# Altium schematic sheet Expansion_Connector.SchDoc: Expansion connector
size A4; Project: STM32MP15-DISCO PI; Date: Not used; ApprovedBy: Not used; CheckedBy: Not used; Author: Not used; CompanyName: STMicroelectronics; DrawnBy: Not used; Engineer: Not used; Organization: Not used; Address1: Not used; Address2: Not used; Address3: Not used; Address4: Not used; DocumentNumber: 14; Revision: Not used; SheetNumber: 14; SheetTotal: 17
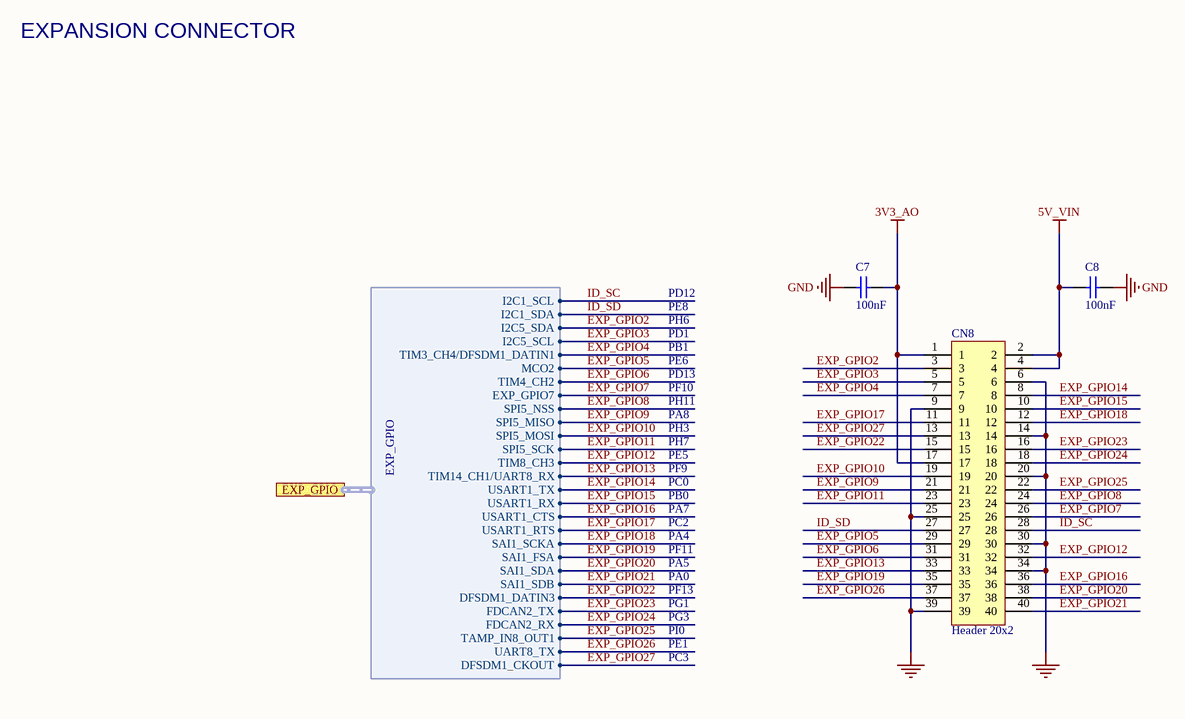
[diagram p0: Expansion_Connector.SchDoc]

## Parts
C7  value 100nF  [C0402]  (hidden comment: Capacitor)
C8  value 100nF  [C0402]  (hidden comment: Capacitor)
CN8  Header 20x2  [CON_SAMTEC_TSW-120-07-G-D]

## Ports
EXP_GPIO (harness EXP_GPIO)

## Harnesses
EXP_GPIO: I2C1_SCL, I2C1_SDA, I2C5_SDA, MCO2, TIM8_CH3, DFSDM1_DATIN3, SPI5_NSS, SPI5_MISO, SPI5_MOSI, SPI5_SCK, TIM4_CH2, USART1_TX, USART1_RX, USART1_CTS, USART1_RTS, UART8_TX, TIM14_CH1/UART8_RX, FDCAN2_TX, FDCAN2_RX, DFSDM1_CKOUT, TIM3_CH4/DFSDM1_DATIN1, I2C5_SCL, SAI1_SCKA, SAI1_FSA, SAI1_SDA, SAI1_SDB, TAMP_IN8_OUT1, EXP_GPIO7

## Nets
3V3_AO: C7.1 CN8.1 CN8.17
5V_VIN: C8.2 CN8.2 CN8.4
GND: C7.2 C8.1 CN8.6 CN8.9 CN8.14 CN8.20 CN8.25 CN8.30 CN8.34 CN8.39
EXP_GPIO2: CN8.3 ; port EXP_GPIO.I2C5_SDA
EXP_GPIO3: CN8.5 ; port EXP_GPIO.I2C5_SCL
EXP_GPIO4: CN8.7 ; port EXP_GPIO.TIM3_CH4/DFSDM1_DATIN1
EXP_GPIO5: CN8.29 ; port EXP_GPIO.MCO2
EXP_GPIO6: CN8.31 ; port EXP_GPIO.TIM4_CH2
EXP_GPIO7: CN8.26 ; port EXP_GPIO.EXP_GPIO7
EXP_GPIO8: CN8.24 ; port EXP_GPIO.SPI5_NSS
EXP_GPIO9: CN8.21 ; port EXP_GPIO.SPI5_MISO
EXP_GPIO10: CN8.19 ; port EXP_GPIO.SPI5_MOSI
EXP_GPIO11: CN8.23 ; port EXP_GPIO.SPI5_SCK
EXP_GPIO12: CN8.32 ; port EXP_GPIO.TIM8_CH3
EXP_GPIO13: CN8.33 ; port EXP_GPIO.TIM14_CH1/UART8_RX
EXP_GPIO14: CN8.8 ; port EXP_GPIO.USART1_TX
EXP_GPIO15: CN8.10 ; port EXP_GPIO.USART1_RX
EXP_GPIO16: CN8.36 ; port EXP_GPIO.USART1_CTS
EXP_GPIO17: CN8.11 ; port EXP_GPIO.USART1_RTS
EXP_GPIO18: CN8.12 ; port EXP_GPIO.SAI1_SCKA
EXP_GPIO19: CN8.35 ; port EXP_GPIO.SAI1_FSA
EXP_GPIO20: CN8.38 ; port EXP_GPIO.SAI1_SDA
EXP_GPIO21: CN8.40 ; port EXP_GPIO.SAI1_SDB
EXP_GPIO22: CN8.15 ; port EXP_GPIO.DFSDM1_DATIN3
EXP_GPIO23: CN8.16 ; port EXP_GPIO.FDCAN2_TX
EXP_GPIO24: CN8.18 ; port EXP_GPIO.FDCAN2_RX
EXP_GPIO25: CN8.22 ; port EXP_GPIO.TAMP_IN8_OUT1
EXP_GPIO26: CN8.37 ; port EXP_GPIO.UART8_TX
EXP_GPIO27: CN8.13 ; port EXP_GPIO.DFSDM1_CKOUT
ID_SC: CN8.28 ; port EXP_GPIO.I2C1_SCL
ID_SD: CN8.27 ; port EXP_GPIO.I2C1_SDA

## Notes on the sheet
- EXPANSION CONNECTOR
- PD12
- PE8
- PB1
- PD1
- PH6
- PE6
- PD13
- PF10
- PA8
- PH3
- PH7
- PH11
- PE5
- PF9
- PA7
- PC0
- PB0
- PF11
- PA4
- PA5
- PA0
- PC2
- PF13
- PG3
- PG1
- PI0
- PE1
- PC3

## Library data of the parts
C7 C8 = MCD-00006: Capacitor, MLCC, 100nF, 16V, X7R, +/-10%, 0402, T=0.5mm; Part_Preference: Recommended; Manufacturer: YAGEO; Manufacturer_Part_Number: CC0402KRX7R7BB104; Partial_Alternate_Internal_Part_Number: MCD-03299; Order_Code_RS: 9402047; Component_Country_Of_Origin: China; ShowFields: YES; ID: 2474
CN8 = MCD-00302: Header, 20x2, 2.54mm, VR, TH, T=5.84mm/2.54mm; Manufacturer_Part_Number: TSW-120-07-G-D; Manufacturer: SAMTEC; Part_Type: Connector; Part_Preference: Recommended; Partial_Alternate_Internal_Part_Number: MCD-04364; Order_Code_RS: 180-2456; Component_Country_Of_Origin: China, Costa Rica, Malaysia, USA, Vietnam; ShowFields: YES; ID: 2567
